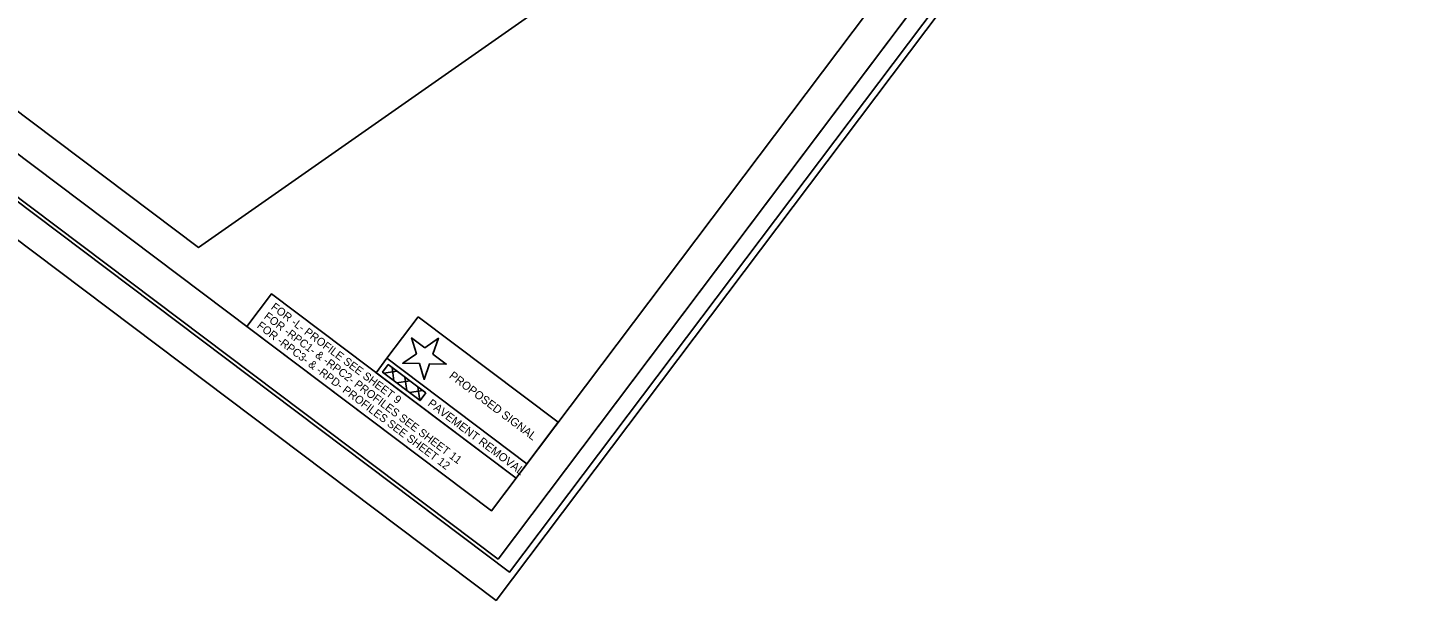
# Model space of a CAD drawing. Extents: x 2296955 to 2298159, y 600182 to 601317.
# Drawn here: x 2297557 to 2298159, y 600182 to 600433 of the extents above; entities that cross this region are included whole.
import ezdxf

# ---------------------------------------------------------------- set-up
doc = ezdxf.new("R2010")
doc.units = 0
for name, color, linetype in [('Default', 7, 'Continuous'), ('Exist DTM Drainline Cogo Comment', 7, 'Continuous'), ('Exist DTM Drainline Cogo Elevation', 7, 'Continuous'), ('Exist DTM Drainline Cogo Point CELL', 7, 'Continuous'), ('Exist Property Iron Pin Cogo Number', 7, 'Continuous'), ('Exist Roads Curbs Cogo Number', 7, 'Continuous'), ('Exist Roads Curbs Cogo Point CELL', 7, 'Continuous'), ('Exist Roads EOP Cogo Comment', 7, 'Continuous'), ('Exist Roads EOP Cogo Elevation', 7, 'Continuous'), ('Exist Roads EOP Cogo Number', 7, 'Continuous')]:
    doc.layers.add(name, color=color, linetype=linetype)

msp = doc.modelspace()

# ---------------------------------------------------------------- linework, layer by layer
at = {"layer": 'Default'}
for p, q in [((2297712.61, 600281.67), (2297718.51, 600282.5)), ((2297716.28, 600284.19), (2297717.11, 600278.28)), ((2297718.25, 600277.42), (2297724.15, 600278.25)), ((2297721.92, 600279.93), (2297722.75, 600274.01)), ((2297727.57, 600275.66), (2297728.4, 600269.75)), ((2297723.88, 600273.16), (2297729.78, 600273.99))]:
    msp.add_line(p, q, dxfattribs=at)
for points in [[(2297727.74, 600306.3), (2297788.94, 600260.17), (2297775.26, 600242.01), (2297714.05, 600288.14)], [(2297714.06, 600288.13), (2297775.26, 600242.01), (2297770.5, 600235.7), (2297709.3, 600281.81)], [(2297731.05, 600273.04), (2297714.64, 600285.43), (2297712.1, 600282.06), (2297728.51, 600269.67)]]:
    msp.add_lwpolyline(points, close=True, dxfattribs=at)
at = {"layer": 'Exist DTM Drainline Cogo Comment'}
msp.add_lwpolyline([(2298148.7, 600700.2), (2297350.15, 601301.97), (2296969.16, 600796.39), (2297767.7, 600194.63)], close=True, dxfattribs=at)
at = {"layer": 'Exist DTM Drainline Cogo Elevation'}
msp.add_lwpolyline([(2298141.78, 600703.5), (2297423.02, 601245.14), (2297043.87, 600742.01), (2297762.63, 600200.36)], close=True, dxfattribs=at)
at = {"layer": 'Exist DTM Drainline Cogo Point CELL'}
msp.add_lwpolyline([(2297730.58, 600292.71), (2297724.79, 600297.07), (2297726.91, 600290.14), (2297720.96, 600285.97), (2297728.23, 600285.84), (2297730.35, 600278.9), (2297732.71, 600285.76), (2297739.97, 600285.64), (2297734.17, 600290.01), (2297736.54, 600296.88), (2297730.58, 600292.71)], dxfattribs=at)
at = {"layer": 'Exist Property Iron Pin Cogo Number'}
msp.add_lwpolyline([(2297342.87, 601088.91), (2297238.27, 600783.77), (2297197.22, 600664.01), (2297465.89, 600461.56), (2297631.65, 600336.65), (2298039.33, 600622.14), (2298039.33, 600622.14), (2297969.72, 600674.6), (2298027.87, 600751.78), (2297428.93, 601203.11)], close=True, dxfattribs=at)
at = {"layer": 'Exist Roads Curbs Cogo Number'}
msp.add_lwpolyline([(2297423.02, 601245.14), (2297043.89, 600742.01), (2297762.65, 600200.36), (2298069.63, 600607.76), (2297973.78, 600679.99), (2298045.93, 600775.73)], close=True, dxfattribs=at)
at = {"layer": 'Exist Roads Curbs Cogo Point CELL'}
msp.add_lwpolyline([(2298158.96, 600709.34), (2297352.03, 601317.42), (2296954.82, 600790.33), (2297761.75, 600182.24)], close=True, dxfattribs=at)
at = {"layer": 'Exist Roads EOP Cogo Comment'}
msp.add_lwpolyline([(2297425.97, 601224.13), (2297064.9, 600744.96), (2297759.7, 600221.37), (2298062.62, 600623.38), (2297966.76, 600695.61), (2298024.92, 600772.78)], close=True, dxfattribs=at)
at = {"layer": 'Exist Roads EOP Cogo Number'}
msp.add_lwpolyline([(2297652.74, 600301.98), (2297759.7, 600221.37), (2297770.5, 600235.7), (2297663.53, 600316.3)], close=True, dxfattribs=at)

# ---------------------------------------------------------------- texts
at = {"layer": 'Exist Roads EOP Cogo Elevation'}
for s, height, rotation, p in [('FOR -L- PROFILE SEE SHEET 9', 3.5, 322.99914, (2297663.03, 600309.92)), ('FOR -RPC1- & -RPC2- PROFILES SEE SHEET 11', 3.5, 322.99914, (2297659.96, 600305.85)), ('FOR -RPC3- & -RPD- PROFILES SEE SHEET 12', 3.5, 322.99914, (2297656.89, 600301.78)), ('PROPOSED SIGNAL', 3.5953, 322.99914, (2297740.92, 600279.87)), ('PAVEMENT REMOVAL', 3.5953, 322.94125, (2297731.59, 600267.75))]:
    msp.add_text(s, height=height, rotation=rotation, dxfattribs=at).set_placement(p)

doc.saveas('drawing.dxf')
